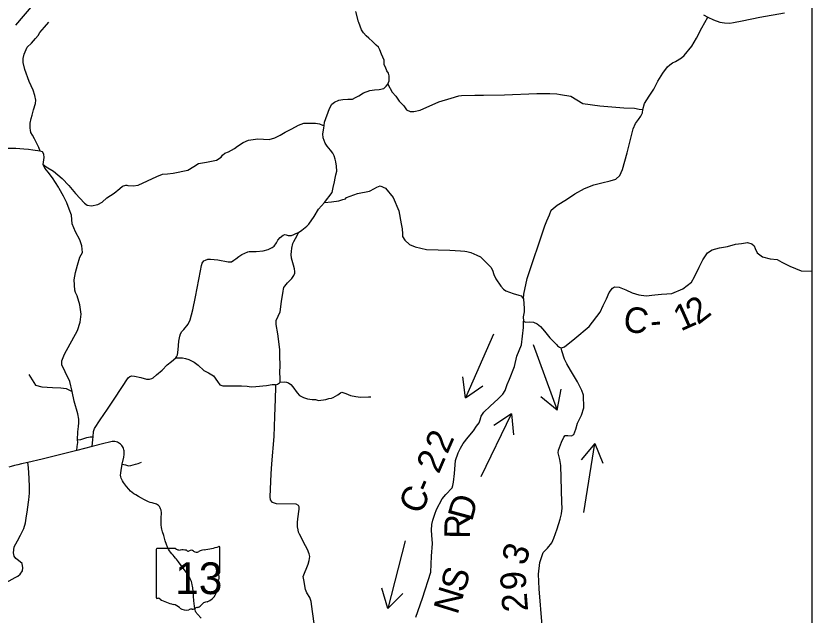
# Model space of a CAD drawing. Extents: x 2025369 to 2161369, y 549489 to 637489.
# Drawn here: x 2074950 to 2092420, y 600839 to 613987 of the extents above; entities that cross this region are included whole.
import ezdxf

# ---------------------------------------------------------------- set-up
doc = ezdxf.new("R2010")
doc.units = 0
for name, color, linetype in [('GM_X_County_Road', 7, 'Continuous'), ('GM_X_State_Route', 7, 'Continuous'), ('GM_X_State_Shield', 7, 'Continuous'), ('GM_X_Township_Road', 7, 'Continuous'), ('GM_X_Township_Road_Text', 7, 'Continuous'), ('GM_X_Township_Subdivision', 7, 'Continuous'), ('SH_Text', 7, 'Continuous')]:
    doc.layers.add(name, color=color, linetype=linetype)

msp = doc.modelspace()

# ---------------------------------------------------------------- linework, layer by layer
at = {"layer": 'GM_X_County_Road'}
for points in [[(2086090, 607778), (2086093, 607878), (2086169, 608224), (2086555, 609379), (2086597, 609492), (2086655, 609620), (2086693, 609721), (2086826, 609837), (2087034, 609959), (2087211, 610080), (2087427, 610198), (2087633, 610280), (2087808, 610327), (2087993, 610365), (2088112, 610405), (2088201, 610487), (2088260, 610617), (2088359, 610981), (2088496, 611506), (2088548, 611627), (2088614, 611714), (2088666, 611789), (2088699, 611863), (2088705, 611934), (2088741, 612065), (2088848, 612225), (2088947, 612379), (2089033, 612554), (2089142, 612728), (2089245, 612871), (2089297, 612915), (2089358, 612955), (2089422, 612986), (2089555, 613070), (2089614, 613117), (2089784, 613326), (2089884, 613496), (2090001, 613724), (2090132, 613963)], [(2076624, 604537), (2076634, 604689), (2076643, 604753), (2076655, 604867), (2076674, 604934), (2076798, 605122), (2076957, 605356), (2077117, 605602), (2077411, 606045), (2077447, 606071), (2077491, 606090), (2077550, 606085), (2077690, 606049), (2077815, 606017), (2077883, 606013), (2077929, 606028), (2077965, 606047), (2078038, 606108), (2078160, 606215), (2078271, 606329), (2078365, 606406), (2078456, 606481), (2078476, 606508), (2078494, 606550), (2078507, 606661), (2078526, 606846), (2078546, 606958), (2078561, 607008), (2078590, 607059), (2078632, 607105), (2078732, 607225), (2078775, 607319), (2078830, 607535), (2078887, 607820), (2078997, 608396), (2079019, 608508), (2079040, 608563), (2079073, 608610), (2079108, 608630), (2079162, 608646), (2079219, 608648), (2079378, 608631), (2079609, 608588), (2079678, 608594), (2079730, 608624), (2079776, 608656), (2079840, 608706), (2079908, 608748), (2080038, 608813), (2080066, 608816), (2080142, 608814), (2080224, 608816), (2080372, 608833), (2080483, 608860), (2080572, 608907), (2080613, 608935), (2080671, 609011), (2080694, 609064), (2080751, 609125), (2080812, 609174), (2080850, 609188), (2080882, 609185), (2080923, 609166), (2080957, 609165), (2080998, 609170), (2081049, 609189), (2081093, 609212), (2081154, 609236), (2081221, 609289), (2081333, 609373), (2081379, 609418), (2081493, 609582), (2081590, 609745), (2081719, 609893), (2081875, 609904), (2082036, 609929), (2082125, 609961), (2082181, 609976), (2082205, 610001), (2082284, 610028), (2082445, 610091), (2082712, 610144), (2082818, 610200), (2082872, 610231), (2082945, 610258), (2083056, 610209), (2083226, 609999), (2083350, 609708), (2083406, 609421), (2083426, 609312), (2083434, 609208), (2083435, 609149), (2083485, 609066), (2083589, 608968), (2083712, 608923), (2083959, 608864), (2084470, 608846), (2084704, 608834), (2084800, 608823)], [(2086911, 606705), (2086942, 606707), (2086990, 606724), (2087214, 606905), (2087529, 607171), (2087767, 607489), (2087836, 607630), (2087909, 607779), (2087970, 607918), (2088044, 608009), (2088086, 608044), (2088186, 608038), (2088333, 607975), (2088474, 607912), (2088621, 607869), (2088777, 607848), (2088971, 607864), (2089114, 607878), (2089232, 607885), (2089346, 607893), (2089582, 607999), (2089771, 608145), (2089843, 608260), (2089944, 608475), (2090021, 608636), (2090124, 608790), (2090229, 608854), (2090388, 608897), (2090565, 608928), (2090740, 608976), (2090871, 608996), (2091003, 609015), (2091099, 608987), (2091146, 608938), (2091174, 608882), (2091217, 608791), (2091331, 608702), (2091498, 608659), (2091654, 608644), (2091753, 608580), (2091929, 608492), (2092179, 608391), (2092420, 608389)], [(2084800, 608823), (2084842, 608818), (2084933, 608796), (2085066, 608739), (2085146, 608698), (2085373, 608475), (2085406, 608410), (2085435, 608315), (2085478, 608221), (2085594, 608056), (2085647, 607994), (2085703, 607952), (2085859, 607894), (2085988, 607858), (2086037, 607841), (2086090, 607778)], [(2086090, 607778), (2086097, 607669), (2086103, 607574), (2086101, 607493), (2086081, 607384), (2086088, 607287)], [(2084100, 602922), (2084106, 602946), (2084141, 603052), (2084182, 603154), (2084302, 603391), (2084380, 603488), (2084520, 603634), (2084537, 603681), (2084549, 603757), (2084574, 603947), (2084598, 604230), (2084651, 604399), (2084708, 604505), (2084767, 604602), (2084876, 604744), (2084990, 604885), (2085059, 604982), (2085112, 605054), (2085140, 605124), (2085157, 605201), (2085218, 605292), (2085356, 605425), (2085535, 605584), (2085635, 605688), (2085683, 605769), (2085730, 605898), (2085778, 606019), (2085888, 606292), (2085943, 606521), (2086041, 606768), (2086086, 607149), (2086088, 607287)], [(2086088, 607287), (2086135, 607267), (2086226, 607273), (2086304, 607269), (2086388, 607228), (2086464, 607169), (2086545, 607068), (2086662, 606923), (2086810, 606775), (2086832, 606748), (2086880, 606715), (2086911, 606705)], [(2075201, 603140), (2075204, 603156), (2075236, 603371), (2075250, 603511), (2075247, 603650), (2075243, 603837), (2075226, 604075), (2075215, 604188)], [(2072889, 601445), (2074237, 601422), (2074428, 601460), (2074674, 601532), (2074801, 601587), (2074934, 601661), (2074989, 601692), (2075042, 601737), (2075093, 601812), (2075103, 601876), (2075088, 601971), (2075006, 602034), (2074947, 602078), (2074910, 602134), (2074895, 602205), (2074910, 602333), (2074984, 602469), (2075050, 602593), (2075125, 602742), (2075162, 602866), (2075183, 603015), (2075201, 603140)], [(2083722, 600793), (2083875, 601207), (2084051, 601778), (2084068, 602132), (2084092, 602413), (2084080, 602594), (2084072, 602704), (2084074, 602826), (2084100, 602922)]]:
    msp.add_lwpolyline(points, dxfattribs=at)
at = {"layer": 'GM_X_State_Route'}
for points in [[(2074949, 613783), (2075328, 614229)], [(2090034, 614014), (2090132, 613963), (2090258, 613903), (2090397, 613852), (2090496, 613835), (2090612, 613831), (2090693, 613839), (2090883, 613877), (2091271, 613957), (2091814, 614053)], [(2077066, 604646), (2077064, 604646), (2077036, 604642), (2077005, 604636), (2076880, 604605), (2076624, 604537), (2076289, 604453), (2076053, 604390), (2075528, 604259), (2075215, 604188), (2075071, 604158), (2074990, 604138), (2074918, 604121), (2074844, 604101), (2074794, 604085)], [(2079013, 600770), (2078932, 600861), (2078922, 600874), (2078911, 600888), (2078900, 600906), (2078891, 600926), (2078881, 600952), (2078873, 600982), (2078865, 601034), (2078853, 601153), (2078836, 601357), (2078829, 601436), (2078824, 601470), (2078818, 601506), (2078810, 601548), (2078801, 601576), (2078790, 601607), (2078777, 601636), (2078761, 601668), (2078726, 601726), (2078690, 601776), (2078579, 601927), (2078516, 602010), (2078494, 602037), (2078473, 602063), (2078450, 602091), (2078425, 602121), (2078400, 602150), (2078373, 602183), (2078344, 602218), (2078318, 602251), (2078299, 602282), (2078276, 602326), (2078254, 602385), (2078227, 602469), (2078192, 602582), (2078168, 602667), (2078154, 602722), (2078146, 602760), (2078139, 602818), (2078137, 602885), (2078140, 603000), (2078142, 603045), (2078143, 603076), (2078142, 603098), (2078138, 603124), (2078134, 603142), (2078126, 603169), (2078114, 603195), (2078097, 603222), (2078077, 603241), (2078055, 603258), (2078033, 603270), (2078013, 603279), (2077985, 603288), (2077939, 603300), (2077899, 603310), (2077861, 603322), (2077812, 603344), (2077754, 603375), (2077702, 603403), (2077642, 603439), (2077582, 603474), (2077537, 603502), (2077503, 603527), (2077465, 603559), (2077425, 603599), (2077377, 603660), (2077333, 603720), (2077312, 603751), (2077291, 603782), (2077276, 603811), (2077263, 603844), (2077254, 603875), (2077248, 603912), (2077249, 603956), (2077258, 604018), (2077274, 604101), (2077284, 604151), (2077316, 604306), (2077325, 604359), (2077328, 604392), (2077328, 604413), (2077324, 604443), (2077320, 604466), (2077312, 604491), (2077302, 604515), (2077290, 604536), (2077275, 604557), (2077258, 604578), (2077247, 604590), (2077226, 604604), (2077201, 604619), (2077176, 604630), (2077152, 604639), (2077118, 604645), (2077087, 604647), (2077066, 604646)]]:
    msp.add_lwpolyline(points, dxfattribs=at)
at = {"layer": 'GM_X_State_Shield'}
for p, q in [((2078030, 602281), (2078030, 601224)), ((2078452, 602299), (2078044, 602299)), ((2079422, 601773), (2079422, 602325)), ((2079422, 601773), (2079422, 601773))]:
    msp.add_line(p, q, dxfattribs=at)
for centre, radius, start, end in [((2078046, 602283), 16.1, 98.1301, 188.1301), ((2078549, 602422), 156, 231.6195, 271.1119), ((2078601, 601706), 562, 80.4867, 94.9883), ((2078728, 602289), 45.1, 219.7921, 297.1024), ((2078794, 602167), 93.8, 54.4667, 119.1411), ((2078915, 602334), 113, 233.8562, 294.8282), ((2079115, 601976), 297, 97.3462, 120.7689), ((2078927, 603740), 1476, 275.8445, 288.9065), ((2079407, 602328), 15.5, 351.8621, 97.738), ((2079419, 601732), 24, 107.944, 210.337), ((2079266, 601662), 144, 340.033, 23.6496), ((2079406, 601770), 16.6, 289.6038, 7.7341), ((2079009, 601471), 369, 292.3089, 8.9858), ((2079478, 601541), 105, 136.8065, 186.9296), ((2078046, 601222), 16.3, 171.9584, 258.3066), ((2078049, 601330), 124, 267.339, 280.6039), ((2078074, 601163), 44.8, 29.7484, 93.2717), ((2078639, 602113), 1066, 240.4129, 257.1985), ((2078322, 600750), 334, 47.1842, 75.836), ((2078682, 601158), 212, 230.7004, 286.2918), ((2078820, 601079), 113, 268.777, 315.5493), ((2078922, 600977), 31.8, 65.7517, 132.6484), ((2078909, 601122), 119, 282.8732, 323.2771), ((2079165, 600928), 202, 94.4031, 142.5768), ((2078805, 600793), 174, 85.6951, 111.2099)]:
    msp.add_arc(centre, radius, start, end, dxfattribs=at)
at = {"layer": 'GM_X_Township_Road'}
for points in [[(2082474, 613845), (2082470, 613857), (2082410, 614084)], [(2075379, 613490), (2075435, 613557), (2075478, 613626), (2075579, 613739), (2075669, 613850)], [(2081719, 609893), (2081886, 610114), (2081912, 610220), (2081938, 610343), (2081952, 610425), (2081971, 610499), (2081989, 610583), (2081987, 610691), (2081973, 610784), (2081956, 610842), (2081932, 610913), (2081901, 610974), (2081854, 611039), (2081780, 611130), (2081739, 611193), (2081712, 611250), (2081689, 611311), (2081687, 611399), (2081704, 611527), (2081712, 611585), (2081722, 611655), (2081828, 611957), (2081880, 612049), (2081941, 612093), (2082032, 612136), (2082126, 612154), (2082231, 612160), (2082335, 612162), (2082405, 612195), (2082476, 612233), (2082579, 612297), (2082714, 612347), (2082821, 612363), (2082921, 612369), (2083020, 612395), (2083071, 612442), (2083109, 612490), (2083137, 612559), (2083142, 612621), (2083137, 612673), (2083126, 612730), (2083091, 612783), (2083057, 612859), (2083032, 612916), (2083032, 613013), (2082975, 613149), (2082934, 613241), (2082904, 613303), (2082857, 613347), (2082777, 613424), (2082693, 613501), (2082635, 613550), (2082576, 613618), (2082534, 613682), (2082474, 613845)], [(2075483, 611022), (2075451, 611096), (2075425, 611156), (2075361, 611290), (2075315, 611371), (2075280, 611426), (2075268, 611480), (2075264, 611521), (2075264, 611632), (2075288, 611737), (2075310, 611810), (2075339, 611926), (2075383, 612066), (2075387, 612137), (2075365, 612244), (2075325, 612359), (2075242, 612549), (2075145, 612814), (2075106, 612967), (2075109, 613054), (2075130, 613148), (2075194, 613300), (2075293, 613386), (2075379, 613490)], [(2083109, 612490), (2083208, 612315), (2083288, 612223), (2083362, 612118), (2083460, 612014), (2083520, 611924), (2083600, 611891), (2083684, 611893), (2083820, 611922), (2084231, 612100), (2084504, 612184), (2084668, 612233), (2084725, 612239), (2085019, 612250)], [(2085019, 612250), (2085027, 612250), (2085212, 612249), (2085668, 612254), (2086380, 612288), (2086668, 612282), (2086817, 612276), (2086903, 612260), (2087127, 612228), (2087387, 612067), (2087762, 612012), (2088293, 611967), (2088521, 611963), (2088625, 611943), (2088705, 611934)], [(2077383, 610270), (2077409, 610268), (2077524, 610255), (2077631, 610272), (2078039, 610461), (2078166, 610515), (2078277, 610523), (2078401, 610535), (2078724, 610603), (2078852, 610681), (2078953, 610747), (2079130, 610777), (2079351, 610819), (2079454, 610889), (2079483, 610929), (2079532, 610974), (2079615, 611004), (2079744, 611080), (2079811, 611129), (2079939, 611207), (2080054, 611258), (2080255, 611291), (2080506, 611278), (2080629, 611315), (2080748, 611369), (2080856, 611437), (2081001, 611506), (2081147, 611588), (2081264, 611634), (2081520, 611633), (2081610, 611621), (2081679, 611591), (2081712, 611585)], [(2075898, 610200), (2075883, 610227), (2075750, 610437), (2075657, 610558), (2075581, 610645), (2075550, 610725), (2075568, 610879), (2075564, 610956), (2075534, 611006), (2075483, 611022), (2075324, 611039), (2075227, 611055), (2075125, 611064), (2074950, 611080), (2074707, 611076)], [(2075550, 610725), (2075612, 610675), (2075772, 610579), (2075962, 610420), (2076108, 610264), (2076260, 610089), (2076456, 609879), (2076511, 609835), (2076610, 609817), (2076750, 609850), (2076843, 609899), (2076948, 609992), (2077104, 610095), (2077228, 610200), (2077289, 610251), (2077359, 610272), (2077383, 610270)], [(2076289, 604453), (2076291, 604539), (2076308, 604628), (2076304, 604687), (2076310, 604857), (2076320, 604980), (2076333, 605058), (2076332, 605139), (2076306, 605257), (2076230, 605536), (2076184, 605743), (2076130, 605963), (2076031, 606177), (2076012, 606228), (2075960, 606323), (2075958, 606421), (2076013, 606565), (2076299, 607084), (2076361, 607269), (2076378, 607440), (2076350, 607649), (2076294, 607846), (2076260, 607921), (2076245, 607971), (2076229, 608196), (2076255, 608360), (2076300, 608517), (2076353, 608693), (2076408, 608798), (2076396, 608942), (2076351, 609074), (2076256, 609251), (2076182, 609424), (2076170, 609617), (2076118, 609749), (2076067, 609883), (2075993, 610031), (2075898, 610200)], [(2080750, 605953), (2080751, 606042), (2080741, 606151), (2080745, 606320), (2080741, 606521), (2080741, 606669), (2080696, 607008), (2080661, 607218), (2080662, 607301), (2080745, 607496), (2080780, 607719), (2080815, 607946), (2080818, 607990), (2080831, 608024), (2080853, 608060), (2080908, 608130), (2081002, 608228), (2081047, 608290), (2081071, 608339), (2081073, 608380), (2081065, 608438), (2081040, 608520), (2080998, 608670), (2080990, 608749), (2081000, 608814), (2081004, 608891), (2081023, 608992), (2081046, 609040), (2081084, 609106), (2081132, 609181), (2081154, 609236)], [(2086495, 600610), (2086433, 601415), (2086416, 601736), (2086447, 601994), (2086521, 602215), (2086617, 602306), (2086713, 602426), (2086751, 602524), (2086830, 602735), (2086896, 602946), (2086920, 603058), (2086935, 603186), (2086927, 603308), (2086908, 604124), (2086882, 604251), (2086862, 604342), (2086849, 604398), (2086854, 604460), (2086920, 604635), (2086976, 604742), (2087005, 604780), (2087063, 604779), (2087141, 604769), (2087189, 604802), (2087236, 604922), (2087270, 605047), (2087357, 605227), (2087411, 605386), (2087404, 605662), (2087371, 605768), (2087270, 605957), (2087117, 606211), (2087037, 606352), (2086986, 606454), (2086928, 606634), (2086911, 606705)], [(2078456, 606481), (2078552, 606483), (2078606, 606482), (2078673, 606469), (2078742, 606446), (2078805, 606419), (2078861, 606390), (2078947, 606323), (2079072, 606204), (2079176, 606158), (2079285, 606089), (2079374, 605968), (2079426, 605893), (2079492, 605873), (2079713, 605873), (2079902, 605871), (2080021, 605863), (2080114, 605851), (2080215, 605853), (2080449, 605880), (2080574, 605895), (2080615, 605899), (2080636, 605897), (2080653, 605889), (2080687, 605909), (2080732, 605934), (2080750, 605953), (2080838, 605960), (2080887, 605953), (2080928, 605938), (2080980, 605899), (2081027, 605844), (2081120, 605719), (2081176, 605660), (2081258, 605616), (2081347, 605586), (2081452, 605573), (2081524, 605572), (2081590, 605549), (2081750, 605571), (2081818, 605590), (2081877, 605601), (2081914, 605611), (2082012, 605674), (2082075, 605715), (2082103, 605727), (2082189, 605698), (2082289, 605660), (2082411, 605636), (2082511, 605623), (2082687, 605630), (2082739, 605630)], [(2075232, 606116), (2075381, 605884), (2075522, 605851), (2075754, 605830), (2075932, 605822), (2076056, 605809), (2076184, 605743)], [(2081540, 600340), (2081461, 600915), (2081431, 601140), (2081400, 601225), (2081333, 601328), (2081307, 601398), (2081268, 601615), (2081254, 601688), (2081364, 601957), (2081388, 602036), (2081402, 602123), (2081388, 602180), (2081347, 602275), (2081307, 602357), (2081270, 602425), (2081228, 602506), (2081169, 602613), (2081153, 602660), (2081141, 602709), (2081131, 602774), (2081130, 602872), (2081135, 602954), (2081164, 603162), (2081163, 603214), (2081150, 603244), (2081099, 603272), (2080671, 603279), (2080581, 603309), (2080537, 603369), (2080532, 603436), (2080553, 603937), (2080562, 604161), (2080616, 604756), (2080629, 605194), (2080644, 605583), (2080656, 605838), (2080653, 605889)]]:
    msp.add_lwpolyline(points, dxfattribs=at)
at = {"layer": 'GM_X_Township_Subdivision'}
for points in [[(2076304, 604687), (2076374, 604692), (2076505, 604736), (2076578, 604748), (2076643, 604753)], [(2077284, 604151), (2077355, 604134), (2077422, 604116), (2077469, 604120), (2077524, 604136), (2077573, 604153), (2077633, 604165), (2077702, 604191)]]:
    msp.add_lwpolyline(points, dxfattribs=at)
at = {"layer": 'SH_Text'}
for p, q in [((2085427, 607005), (2084814, 605603)), ((2086297, 606773), (2086829, 605339)), ((2084814, 605603), (2084755, 606066)), ((2084814, 605603), (2085195, 605873)), ((2086829, 605339), (2086915, 605797)), ((2086829, 605339), (2086465, 605630)), ((2085161, 603879), (2085825, 605257)), ((2085825, 605257), (2085435, 605001)), ((2085825, 605257), (2085868, 604792)), ((2087656, 604604), (2087355, 604247)), ((2087413, 603093), (2087656, 604604)), ((2087656, 604604), (2087829, 604171)), ((2083489, 602468), (2083108, 600986)), ((2083108, 600986), (2082976, 601433)), ((2083108, 600986), (2083440, 601314))]:
    msp.add_line(p, q, dxfattribs=at)
msp.add_lwpolyline([(2037369, 631489), (2037369, 571561), (2092420, 571561), (2092420, 631489)], dxfattribs=at)

# ---------------------------------------------------------------- texts
at = {"layer": 'GM_X_State_Shield'}
msp.add_text('13', height=696.1, dxfattribs=at).set_placement((2078445, 601299))
at = {"layer": 'GM_X_Township_Road_Text'}
for s, rotation, p in [('2', 37.8081, (2089917, 607195)), ('C', 352.293, (2088255, 607071)), ('1', 24.0886, (2089537, 607059)), ('-', 5.3075, (2088889, 607013)), ('D', 74.8283, (2084957, 602875)), ('R', 89.0459, (2084909, 602509)), ('3', 71.3866, (2086120, 601903)), ('S', 72.8608, (2084787, 601313)), ('9', 93.1351, (2086153, 601403)), ('N', 72.8608, (2084637, 600829)), ('2', 94.3978, (2086190, 600928))]:
    msp.add_text(s, height=560, rotation=rotation, dxfattribs=at).set_placement(p)
at = {"layer": 'SH_Text'}
for s, p in [('2', (2084416, 604355)), ('2', (2084227, 603918)), ('-', (2084042, 603493)), ('C', (2083839, 603024))]:
    msp.add_text(s, height=560, rotation=66.5477, dxfattribs=at).set_placement(p)

doc.saveas('drawing.dxf')
